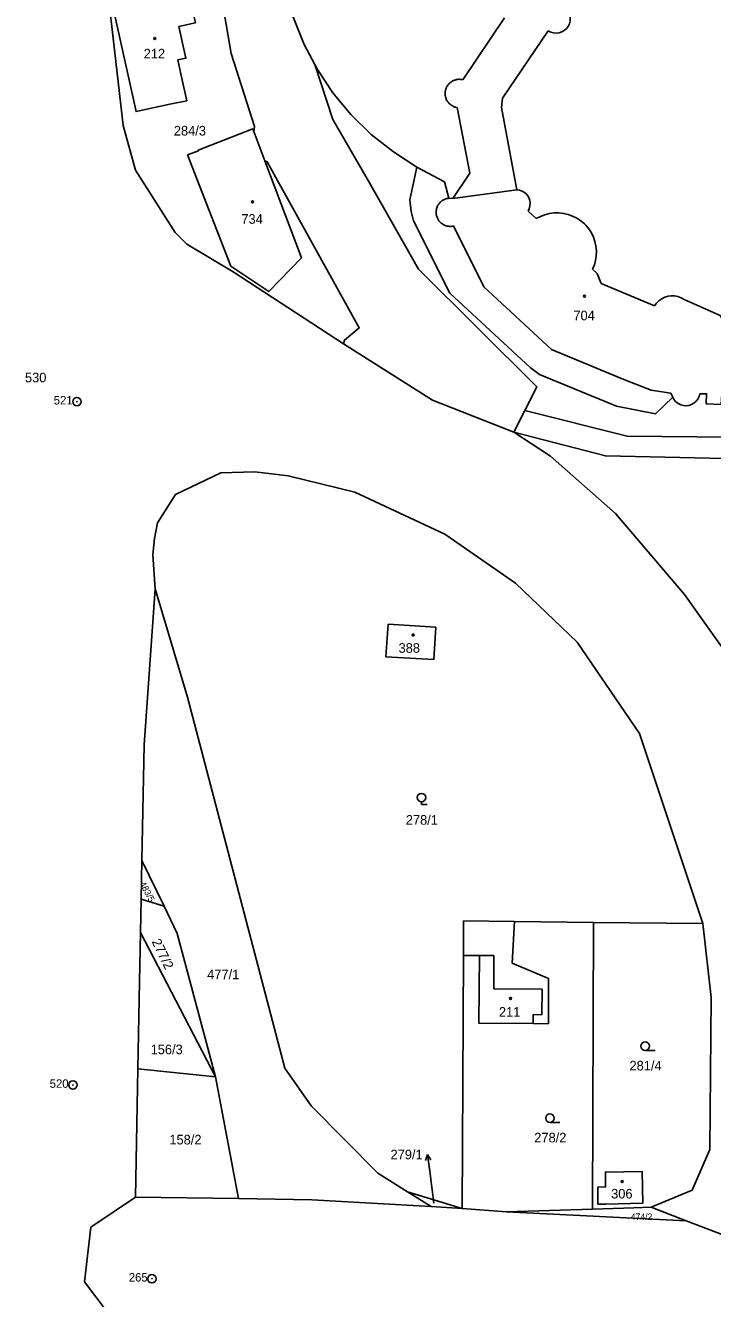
# Model space of a CAD drawing. Extents: x -725728 to -720881, y -1068679 to -1063504.
# Drawn here: x -724891.3 to -724769.7, y -1067027.7 to -1066802.4 of the extents above; entities that cross this region are included whole.
import ezdxf

# ---------------------------------------------------------------- set-up
doc = ezdxf.new("R2010")
doc.units = 0
for name, color, linetype in [('Hranice parcel', 7, 'Continuous'), ('Parcelní čísla', 7, 'Continuous'), ('Pop  PČ popisy', 7, 'Continuous'), ('Vnitřní kresba', 7, 'Continuous'), ('Značky bodu BP', 7, 'Continuous'), ('Značky budov', 7, 'Continuous'), ('Značky kultur', 7, 'Continuous')]:
    doc.layers.add(name, color=color, linetype=linetype)

# ---------------------------------------------------------------- blocks, each defined once
blk = doc.blocks.new('4.02_3')
at = {"layer": 'Značky budov'}
blk.add_circle((-0.001, 0), 0.0175, dxfattribs=at)
blk = doc.blocks.new('4.02_4')
at = {"layer": 'Značky budov'}
blk.add_circle((-0.001, 0), 0.0175, dxfattribs=at)
blk = doc.blocks.new('1029_96')
at = {"layer": 'Pop  PČ popisy'}
for p, q in [((-0.042, 0.297), (-0.077, 0.191)), ((0, 0), (-0.042, 0.297)), ((-0.042, 0.297), (0.022, 0.205))]:
    blk.add_line(p, q, dxfattribs=at)
blk = doc.blocks.new('3.05_1')
at = {"layer": 'Značky kultur'}
for p, q in [((0, 0.05), (0, 0)), ((0, 0), (0.1, 0))]:
    blk.add_line(p, q, dxfattribs=at)
blk.add_circle((0, 0.125), 0.075, dxfattribs=at)
blk = doc.blocks.new('3.04_2')
at = {"layer": 'Značky kultur'}
blk.add_line((0.001, 0), (0.176, 0), dxfattribs=at)
blk.add_circle((0.001, 0.075), 0.075, dxfattribs=at)
blk = doc.blocks.new('1.01_1')
at = {"layer": 'Značky bodu BP'}
for radius in [0.075, 0.003]:
    blk.add_circle((0, 0), radius, dxfattribs=at)

msp = doc.modelspace()

# ---------------------------------------------------------------- linework, layer by layer
at = {"layer": 'Hranice parcel'}
for p, q in [((-724850.93, -1066821.21), (-724848.97, -1066826.4)), ((-724800.92, -1066836.63), (-724802.38, -1066835.32)), ((-724779.98, -1066852.07), (-724789.45, -1066848.11)), ((-724802.93, -1066870.58), (-724804.87, -1066874.4)), ((-724870.71, -1066950.22), (-724870.84, -1066957.04)), ((-724870.71, -1066950.22), (-724866.8, -1066958.32)), ((-724870.96, -1066962.96), (-724870.84, -1066957.04)), ((-724870.84, -1066957.04), (-724866.8, -1066958.32)), ((-724804.77, -1066961.02), (-724790.77, -1066961.17)), ((-724790.97, -1067011.91), (-724790.77, -1066961.17)), ((-724790.77, -1066961.17), (-724771.45, -1066961.38)), ((-724857.67, -1066988.49), (-724870.96, -1066962.96)), ((-724814.06, -1067011.78), (-724813.81, -1066967)), ((-724871.42, -1066987.11), (-724871.87, -1067009.8)), ((-724871.42, -1066987.11), (-724857.67, -1066988.49)), ((-724853.61, -1067010), (-724857.67, -1066988.49)), ((-724871.87, -1067009.8), (-724853.61, -1067010)), ((-724823.71, -1067008.83), (-724819.54, -1067011.47)), ((-724823.71, -1067008.83), (-724814.06, -1067011.78)), ((-724790.05, -1067008), (-724790.01, -1067011.05)), ((-724819.54, -1067011.47), (-724814.06, -1067011.78)), ((-724814.06, -1067011.78), (-724806.16, -1067012.39)), ((-724806.16, -1067012.39), (-724790.97, -1067011.91)), ((-724774.4, -1067013.95), (-724780.59, -1067011.57)), ((-724806.16, -1067012.39), (-724774.4, -1067013.95))]:
    msp.add_line(p, q, dxfattribs=at)
for points in [[(-724873.27, -1066753.87), (-724875.46, -1066785.25), (-724876.2, -1066801.12), (-724874.04, -1066820.14), (-724871.87, -1066828.07), (-724864.85, -1066839.09), (-724862.75, -1066841.16), (-724854.54, -1066846.06), (-724835.04, -1066858.79)], [(-724856.36, -1066798.86), (-724859.03, -1066799.42), (-724858.99, -1066799.58), (-724861.66, -1066800.21), (-724861.25, -1066801.97), (-724864.16, -1066802.61), (-724862.92, -1066808.25), (-724864.38, -1066808.55), (-724863.67, -1066811.81), (-724862.75, -1066815.76), (-724865.75, -1066816.37), (-724871.74, -1066817.68), (-724875.83, -1066799.1), (-724875.71, -1066797.56), (-724860.41, -1066794.3), (-724860.72, -1066792.86), (-724857.48, -1066792.17)], [(-724850.93, -1066821.21), (-724850.78, -1066820.31), (-724854.93, -1066807.41), (-724856.36, -1066798.86)], [(-724840.1, -1066809.37), (-724842.02, -1066805.8), (-724844, -1066800.81), (-724843.2, -1066799.95)], [(-724797.86, -1066798.81), (-724797.36, -1066798.77), (-724796.86, -1066798.84), (-724796.39, -1066799), (-724795.95, -1066799.25), (-724795.58, -1066799.58), (-724795.28, -1066799.98), (-724795.06, -1066800.44), (-724794.94, -1066800.92), (-724794.91, -1066801.43), (-724794.94, -1066801.67), (-724795.06, -1066802.16), (-724795.28, -1066802.61), (-724795.59, -1066803.01), (-724795.96, -1066803.34), (-724796.4, -1066803.59), (-724796.87, -1066803.75), (-724797.37, -1066803.81), (-724797.87, -1066803.77), (-724798.35, -1066803.63), (-724798.8, -1066803.4)], [(-724798.8, -1066803.4), (-724806.89, -1066815.32), (-724807.06, -1066816.96), (-724804.36, -1066831.52)], [(-724822.08, -1066827.5), (-724826.21, -1066824.81), (-724830.12, -1066821.72), (-724833.71, -1066818.18), (-724836.92, -1066814.34), (-724839.64, -1066810.24), (-724840.1, -1066809.37)], [(-724840.1, -1066809.37), (-724836.9, -1066819.1), (-724830.44, -1066830.3), (-724821.76, -1066845.56), (-724800.81, -1066866.4), (-724802.93, -1066870.58)], [(-724848.97, -1066826.4), (-724842.49, -1066843.58), (-724848.25, -1066849.55), (-724854.98, -1066845.02), (-724862.64, -1066825.36), (-724860.7, -1066824.61), (-724860.74, -1066824.51), (-724851.1, -1066820.76), (-724850.93, -1066821.21)], [(-724835.04, -1066858.79), (-724834.85, -1066858.12), (-724832.24, -1066855.98), (-724848.54, -1066826.56), (-724848.97, -1066826.4)], [(-724822.08, -1066827.5), (-724823.3, -1066833.3), (-724823.08, -1066835.37), (-724822.62, -1066837.01), (-724816.23, -1066849.82), (-724801.99, -1066862.96), (-724800.35, -1066864.24), (-724786.73, -1066869.82), (-724779.81, -1066871.16), (-724776.77, -1066868.24)], [(-724804.36, -1066831.52), (-724815.66, -1066833.07), (-724816.38, -1066833.02), (-724817.15, -1066830.1), (-724822.08, -1066827.5)], [(-724802.38, -1066835.32), (-724802.16, -1066834.87), (-724802.03, -1066834.39), (-724802, -1066833.89), (-724802.08, -1066833.4), (-724802.12, -1066833.23), (-724802.32, -1066832.78), (-724802.61, -1066832.37), (-724802.97, -1066832.03), (-724803.4, -1066831.77), (-724803.87, -1066831.59), (-724804.36, -1066831.52)], [(-724790.94, -1066845.6), (-724790.63, -1066844.82), (-724790.41, -1066844.02), (-724790.29, -1066843.19), (-724790.27, -1066842.35), (-724790.35, -1066841.52), (-724790.53, -1066840.7), (-724790.81, -1066839.91), (-724791.17, -1066839.16), (-724791.63, -1066838.46), (-724792.16, -1066837.81), (-724792.41, -1066837.56), (-724793.05, -1066837.02), (-724793.74, -1066836.55), (-724794.49, -1066836.18), (-724795.28, -1066835.89), (-724796.09, -1066835.7), (-724796.92, -1066835.61), (-724797.76, -1066835.62), (-724798.59, -1066835.73), (-724799.4, -1066835.93), (-724800.18, -1066836.24), (-724800.92, -1066836.63)], [(-724789.45, -1066848.11), (-724790.12, -1066846.34), (-724790.94, -1066845.6)], [(-724774.77, -1066850.94), (-724775.3, -1066850.64), (-724775.86, -1066850.43), (-724776.46, -1066850.32), (-724777.06, -1066850.3), (-724777.58, -1066850.37), (-724778.16, -1066850.54), (-724778.7, -1066850.8), (-724779.2, -1066851.15), (-724779.63, -1066851.58), (-724779.98, -1066852.07)], [(-724767.81, -1066854.73), (-724768.38, -1066853.76), (-724774.77, -1066850.94)], [(-724804.87, -1066874.4), (-724806.83, -1066873.64), (-724819.3, -1066868.78), (-724835.04, -1066858.79)], [(-724771.97, -1066867.63), (-724770.78, -1066867.63), (-724770.83, -1066869.42), (-724768.17, -1066869.5), (-724768.1, -1066867.7), (-724767.3, -1066867.72), (-724767.12, -1066858.75)], [(-724776.77, -1066868.24), (-724776.53, -1066868.68), (-724776.2, -1066869.06), (-724775.8, -1066869.37), (-724775.35, -1066869.59), (-724774.87, -1066869.72), (-724774.42, -1066869.75), (-724773.92, -1066869.7), (-724773.44, -1066869.54), (-724773.01, -1066869.29), (-724772.63, -1066868.96), (-724772.32, -1066868.57), (-724772.1, -1066868.12), (-724771.97, -1066867.63)], [(-724802.93, -1066870.58), (-724784.83, -1066875.12), (-724723.29, -1066875.69)], [(-724804.87, -1066874.4), (-724798.38, -1066878.66), (-724786.89, -1066888.79), (-724774.71, -1066903.17), (-724764.22, -1066917.83), (-724755.72, -1066938.49), (-724752.34, -1066950.29), (-724749.37, -1066959.17)], [(-724751.78, -1066879.41), (-724788.68, -1066878.61), (-724804.87, -1066874.4)], [(-724771.45, -1066961.38), (-724782.62, -1066927.75), (-724793.68, -1066911.55), (-724804.6, -1066901.11), (-724817.12, -1066892.45), (-724833, -1066885.05), (-724844.81, -1066882.14), (-724850.74, -1066881.45), (-724856.72, -1066881.62), (-724864.79, -1066885.44), (-724867.96, -1066890.45), (-724868.5, -1066893.25), (-724868.78, -1066896.14), (-724868.36, -1066902.14)], [(-724868.36, -1066902.14), (-724870.31, -1066929.77), (-724870.71, -1066950.22)], [(-724868.36, -1066902.14), (-724862.65, -1066921.32), (-724845.42, -1066986.94), (-724840.76, -1066993.62), (-724828.94, -1067005.52), (-724823.71, -1067008.83)], [(-724818.7, -1066908.93), (-724819.05, -1066914.66), (-724827.52, -1066914.16), (-724827.11, -1066908.42), (-724818.7, -1066908.93)], [(-724866.8, -1066958.32), (-724864.47, -1066963.15), (-724857.67, -1066988.49)], [(-724804.77, -1066961.02), (-724813.77, -1066960.92), (-724813.81, -1066967)], [(-724813.81, -1066967), (-724810.99, -1066967.02), (-724811.06, -1066979.02), (-724801.45, -1066979.07), (-724798.77, -1066979.09), (-724798.73, -1066971.09), (-724805.18, -1066968.38), (-724804.77, -1066961.02)], [(-724780.59, -1067011.57), (-724773.35, -1067008.53), (-724770.17, -1067001.33), (-724769.96, -1066974.45), (-724771.45, -1066961.38)], [(-724870.96, -1066962.96), (-724871.13, -1066971.61), (-724871.42, -1066987.11)], [(-724790.01, -1067011.05), (-724788.59, -1067011.02), (-724782.07, -1067010.86), (-724782.17, -1067005.26), (-724788.68, -1067005.35), (-724788.65, -1067007.99), (-724790.05, -1067008)], [(-724872.82, -1067035.37), (-724880.89, -1067024.75), (-724879.73, -1067015.08), (-724871.87, -1067009.8)], [(-724853.61, -1067010), (-724840.66, -1067010.28), (-724819.54, -1067011.47)], [(-724790.97, -1067011.91), (-724783.66, -1067011.69), (-724780.59, -1067011.57)], [(-724774.4, -1067013.95), (-724764.03, -1067017.93), (-724742.59, -1067019.76), (-724719.69, -1067026.09), (-724719.5, -1067017.82)]]:
    msp.add_lwpolyline(points, dxfattribs=at)
at = {"layer": 'Pop  PČ popisy'}
msp.add_line((-724819.02, -1067010.86), (-724819.77, -1067005.21), dxfattribs=at)
at = {"layer": 'Vnitřní kresba'}
for p, q in [((-724806.53, -1066801.12), (-724813.93, -1066812.06)), ((-724814.91, -1066816.97), (-724812.7, -1066828.57)), ((-724812.7, -1066828.57), (-724815.66, -1066833.07)), ((-724815.54, -1066837.93), (-724810.19, -1066848.67)), ((-724810.19, -1066848.67), (-724798.21, -1066859.8)), ((-724798.21, -1066859.8), (-724785.44, -1066865.07)), ((-724785.44, -1066865.07), (-724780.58, -1066867.01)), ((-724780.58, -1066867.01), (-724777.1, -1066867.53)), ((-724777.1, -1066867.53), (-724776.77, -1066868.24)), ((-724810.99, -1066967.02), (-724808.41, -1066967.03)), ((-724808.41, -1066967.03), (-724808.45, -1066972.93)), ((-724808.45, -1066972.93), (-724799.9, -1066972.98)), ((-724799.9, -1066972.98), (-724799.95, -1066977.5)), ((-724801.44, -1066977.49), (-724801.45, -1066979.07)), ((-724799.95, -1066977.5), (-724801.44, -1066977.49))]:
    msp.add_line(p, q, dxfattribs=at)
for points in [[(-724813.93, -1066812.06), (-724814.07, -1066812.03), (-724814.21, -1066812.01), (-724814.35, -1066811.99), (-724814.48, -1066811.98), (-724814.62, -1066811.98), (-724814.77, -1066811.99), (-724814.9, -1066812.01), (-724815.04, -1066812.03), (-724815.18, -1066812.06), (-724815.31, -1066812.1), (-724815.45, -1066812.15), (-724815.58, -1066812.2), (-724815.7, -1066812.26), (-724815.83, -1066812.33), (-724815.94, -1066812.41), (-724816.06, -1066812.49), (-724816.17, -1066812.58), (-724816.27, -1066812.67), (-724816.37, -1066812.77), (-724816.46, -1066812.87), (-724816.55, -1066812.98), (-724816.63, -1066813.1), (-724816.71, -1066813.22), (-724816.78, -1066813.34), (-724816.84, -1066813.47), (-724816.89, -1066813.59), (-724816.94, -1066813.73), (-724816.97, -1066813.86), (-724817.01, -1066814), (-724817.03, -1066814.14), (-724817.05, -1066814.28), (-724817.05, -1066814.42), (-724817.05, -1066814.56), (-724817.05, -1066814.7), (-724817.03, -1066814.84), (-724817.01, -1066814.98), (-724816.98, -1066815.11), (-724816.94, -1066815.25), (-724816.89, -1066815.38), (-724816.84, -1066815.51), (-724816.78, -1066815.64), (-724816.71, -1066815.76), (-724816.64, -1066815.88), (-724816.56, -1066815.99), (-724816.47, -1066816.1), (-724816.38, -1066816.21), (-724816.28, -1066816.31), (-724816.17, -1066816.4), (-724816.06, -1066816.49), (-724815.95, -1066816.57), (-724815.83, -1066816.64), (-724815.71, -1066816.71), (-724815.58, -1066816.77), (-724815.45, -1066816.83), (-724815.32, -1066816.88), (-724815.19, -1066816.91), (-724815.05, -1066816.95), (-724814.91, -1066816.97)], [(-724816.38, -1066833.02), (-724816.52, -1066833.04), (-724816.66, -1066833.06), (-724816.79, -1066833.09), (-724816.92, -1066833.13), (-724817.06, -1066833.18), (-724817.18, -1066833.24), (-724817.31, -1066833.3), (-724817.43, -1066833.37), (-724817.55, -1066833.44), (-724817.66, -1066833.52), (-724817.77, -1066833.61), (-724817.87, -1066833.7), (-724817.97, -1066833.8), (-724818.06, -1066833.91), (-724818.15, -1066834.02), (-724818.23, -1066834.13), (-724818.3, -1066834.25), (-724818.37, -1066834.37), (-724818.43, -1066834.5), (-724818.48, -1066834.63), (-724818.52, -1066834.76), (-724818.56, -1066834.89), (-724818.59, -1066835.03), (-724818.61, -1066835.17), (-724818.63, -1066835.3), (-724818.64, -1066835.44), (-724818.64, -1066835.58), (-724818.63, -1066835.72), (-724818.61, -1066835.86), (-724818.59, -1066836), (-724818.56, -1066836.13), (-724818.52, -1066836.27), (-724818.47, -1066836.4), (-724818.42, -1066836.53), (-724818.36, -1066836.65), (-724818.29, -1066836.77), (-724818.22, -1066836.89), (-724818.14, -1066837), (-724818.05, -1066837.11), (-724817.96, -1066837.22), (-724817.86, -1066837.32), (-724817.76, -1066837.41), (-724817.65, -1066837.5), (-724817.54, -1066837.58), (-724817.42, -1066837.65), (-724817.3, -1066837.72), (-724817.17, -1066837.78), (-724817.04, -1066837.83), (-724816.91, -1066837.88), (-724816.78, -1066837.92), (-724816.64, -1066837.95), (-724816.51, -1066837.98), (-724816.37, -1066837.99), (-724816.23, -1066838), (-724816.09, -1066838), (-724815.95, -1066838), (-724815.81, -1066837.98), (-724815.68, -1066837.96), (-724815.54, -1066837.93)]]:
    msp.add_lwpolyline(points, dxfattribs=at)

# ---------------------------------------------------------------- block references
at = {"layer": 'Pop  PČ popisy', "xscale": 10, "yscale": 10}
msp.add_blockref('1029_96', (-724819.77, -1067005.21), dxfattribs=at)
at = {"layer": 'Značky bodu BP', "xscale": 10, "yscale": 10}
for p in [(-724882.21, -1066869.02), (-724882.92, -1066989.94), (-724868.93, -1067024.23)]:
    msp.add_blockref('1.01_1', p, dxfattribs=at)
at = {"layer": 'Značky budov', "xscale": 10, "yscale": 10}
for name, p in [('4.02_3', (-724868.43, -1066804.75)), ('4.02_4', (-724851.14, -1066833.64)), ('4.02_3', (-724792.38, -1066850.36)), ('4.02_3', (-724822.71, -1066910.31)), ('4.02_3', (-724805.46, -1066974.61)), ('4.02_3', (-724785.7, -1067007.03))]:
    msp.add_blockref(name, p, dxfattribs=at)
at = {"layer": 'Značky kultur', "xscale": 10, "yscale": 10}
for name, p in [('3.05_1', (-724821.24, -1066940.33)), ('3.04_2', (-724781.65, -1066983.82)), ('3.04_2', (-724798.5, -1066996.55))]:
    msp.add_blockref(name, p, dxfattribs=at)

# ---------------------------------------------------------------- texts
at = {"layer": 'Parcelní čísla'}
for s, height, p in [('212', 1.7, (-724870.4, -1066808.28)), ('284/3', 1.7, (-724865.06, -1066821.92)), ('734', 1.7, (-724853.11, -1066837.54)), ('704', 1.7, (-724794.35, -1066854.62)), ('530', 1.7, (-724891.41, -1066865.6)), ('388', 1.7, (-724825.29, -1066913.46)), ('278/1', 1.7, (-724824.01, -1066943.88)), ('477/1', 1.7, (-724859.16, -1066971.22)), ('211', 1.7, (-724807.52, -1066977.86)), ('156/3', 1.7, (-724869.17, -1066984.5)), ('281/4', 1.7, (-724784.42, -1066987.37)), ('158/2', 1.7, (-724865.85, -1067000.46)), ('278/2', 1.7, (-724801.27, -1067000.1)), ('279/1', 1.7, (-724826.71, -1067003.09)), ('306', 1.7, (-724787.67, -1067010.03)), ('474/2', 1.14, (-724784.19, -1067013.82))]:
    msp.add_text(s, height=height, dxfattribs=at).set_placement(p)
for s, height, rotation, p in [('483/5', 1.14, 298, (-724871.15, -1066954.31)), ('277/2', 1.7, 296, (-724869.03, -1066964.56))]:
    msp.add_text(s, height=height, rotation=rotation, dxfattribs=at).set_placement(p)
at = {"layer": 'Značky bodu BP'}
for s, p in [('521', (-724886.32, -1066869.52)), ('520', (-724887.03, -1066990.44)), ('265', (-724873.03, -1067024.73))]:
    msp.add_text(s, height=1.5, dxfattribs=at).set_placement(p)

doc.saveas('drawing.dxf')
